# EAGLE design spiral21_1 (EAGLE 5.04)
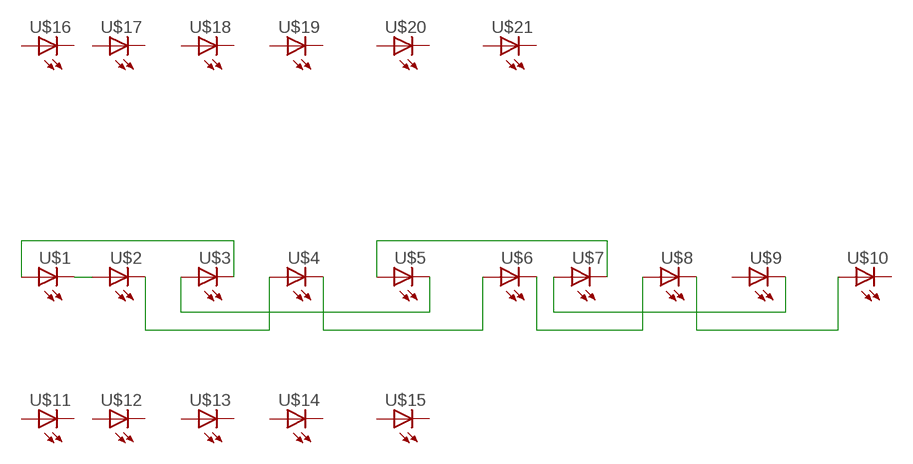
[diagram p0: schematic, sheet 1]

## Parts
U$1  LED5MM  [LED5MM]
U$2  LED5MM  [LED5MM]
U$3  LED5MM  [LED5MM]
U$4  LED5MM  [LED5MM]
U$5  LED5MM  [LED5MM]
U$6  LED5MM  [LED5MM]
U$7  LED5MM  [LED5MM]
U$8  LED5MM  [LED5MM]
U$9  LED5MM  [LED5MM]
U$10  LED5MM  [LED5MM]
U$11  LED5MM  [LED5MM]
U$12  LED5MM  [LED5MM]
U$13  LED5MM  [LED5MM]
U$14  LED5MM  [LED5MM]
U$15  LED5MM  [LED5MM]
U$16  LED5MM  [LED5MM]
U$17  LED5MM  [LED5MM]
U$18  LED5MM  [LED5MM]
U$19  LED5MM  [LED5MM]
U$20  LED5MM  [LED5MM]
U$21  LED5MM  [LED5MM]

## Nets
N$1: U$1.K(C) U$2.A
N$2: U$2.K(C) U$4.A
N$3: U$4.K(C) U$6.A
N$4: U$6.K(C) U$8.A
N$5: U$8.K(C) U$10.A
N$6: U$1.A U$3.K(C)
N$7: U$3.A U$5.K(C)
N$8: U$5.A U$7.K(C)
N$9: U$7.A U$9.K(C)
Unconnected: U$9.A U$10.K(C) U$11.A U$11.K(C) U$12.A U$12.K(C) U$13.A U$13.K(C) U$14.A U$14.K(C) U$15.A U$15.K(C) U$16.A U$16.K(C) U$17.A U$17.K(C) U$18.A U$18.K(C) U$19.A U$19.K(C) U$20.A U$20.K(C) U$21.A U$21.K(C)

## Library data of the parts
U$1-U$21 = led(2):LED: LED

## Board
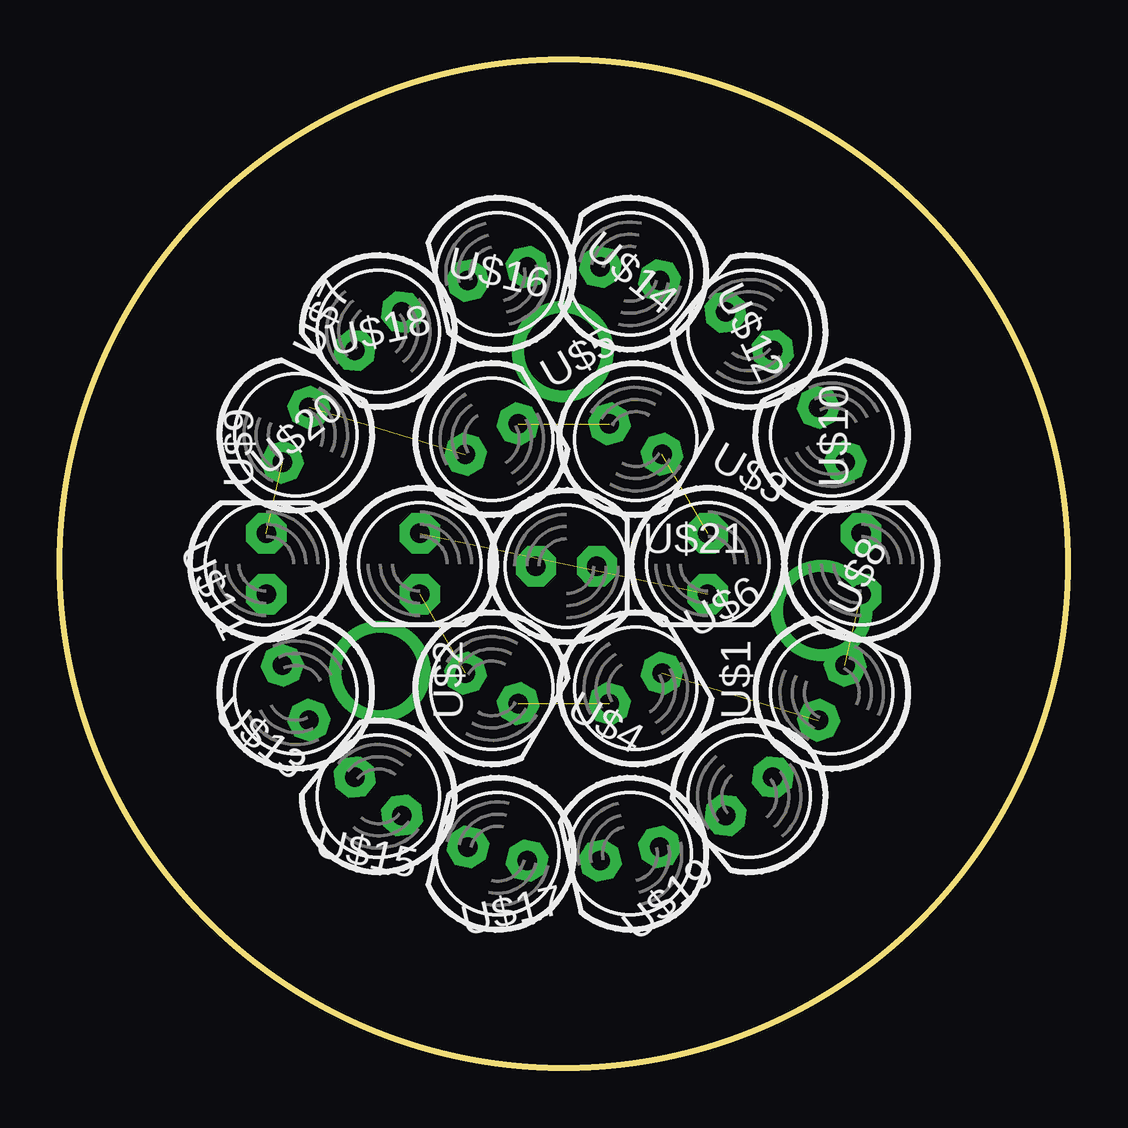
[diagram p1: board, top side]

Size 42 x 42 mm. Coordinates in mm from the lower left corner, seen from the top.
Outline: circle at 21,21 radius 21
Copper layers (1*16): Top 0.035mm / dielectric 1.5mm / Bottom 0.035mm
Design rules "default": minimum track width 10mil, minimum drill 24mil, track to track 8mil, track to pad 8mil, pad to pad 8mil, via to via 8mil, smd to smd 8mil, copper to edge 40mil, drill to drill 8mil, minimum pad ring 10mil, minimum via ring 8mil, stop-mask expansion 4mil, vias tented up to drill 0mil, thermal gap 10mil

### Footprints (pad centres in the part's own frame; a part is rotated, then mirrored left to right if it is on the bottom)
LED5MM = drill 0.813 pad 1.676 octagon: A -1.27,0; K 1.27,0

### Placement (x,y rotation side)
U$1  27,21 270 top
U$2  15,21 270 top
U$3  24,26.2 330 top
U$4  18,15.8 330 top
U$5  18,26.2 30 top
U$6  24,15.8 30 top
U$7  9.83,26.38 64 top
U$8  32.17,15.62 64 top
U$9  8.6,21 90 top
U$10  33.4,21 90 top
U$11  9.83,15.62 116 top
U$12  32.17,26.38 116 top
U$13  13.27,11.31 141 top
U$14  28.73,30.69 141 top
U$15  18.24,8.91 167 top
U$16  23.76,33.09 167 top
U$17  23.76,8.91 193 top
U$18  18.24,33.09 193 top
U$19  28.73,11.31 219 top
U$20  13.27,30.69 219 top
U$21  21.11,20.9 0 top

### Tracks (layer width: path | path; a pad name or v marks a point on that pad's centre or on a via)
N$1  (1 unrouted)
N$2  (1 unrouted)
N$3  (1 unrouted)
N$4  (1 unrouted)
N$5  (1 unrouted)
N$6  (1 unrouted)
N$7  (1 unrouted)
N$8  (1 unrouted)
N$9  (1 unrouted)
N$10  (via drill 3.2)
  other vias: 20.95,29.84
N$11  (via drill 3.2)
  other vias: 13.34,16.51
N$12  (via drill 3.2)
  other vias: 31.75,19.05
